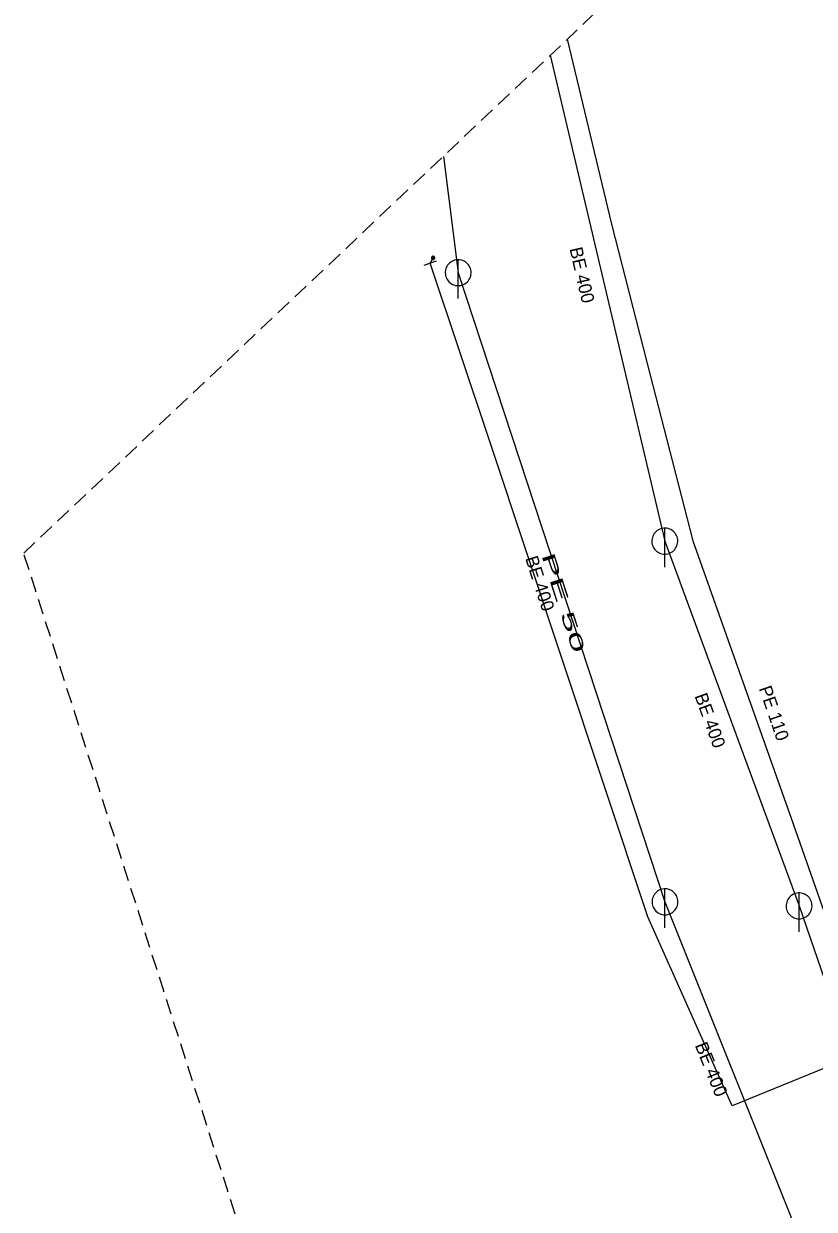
# Model space of a CAD drawing. Extents: x -779496 to -779026, y -977086 to -976624.
# Drawn here: x -779496.1 to -779435.1, y -977014.1 to -976922.6 of the extents above; entities that cross this region are included whole.
import ezdxf

# ---------------------------------------------------------------- set-up
doc = ezdxf.new("R2010")
doc.units = 0
doc.header["$LTSCALE"] = 0.4
doc.linetypes.add('MEDIUM_DASHED', pattern=[4.5, 3, -1.5])
for name, color, linetype, lineweight in [('1', 7, 'MEDIUM_DASHED', 25), ('14', 7, 'Continuous', 13), ('17', 7, 'Continuous', 25), ('22', 7, 'Continuous', 13), ('34', 7, 'Continuous', 13), ('9', 7, 'Continuous', 13)]:
    doc.layers.add(name, color=color, linetype=linetype, lineweight=lineweight)

msp = doc.modelspace()

# ---------------------------------------------------------------- linework, layer by layer
at = {"layer": '1'}
msp.add_lwpolyline([(-779144.045, -976624.23), (-779025.876, -976692.559), (-779211.57, -976955.425), (-779456.75, -977086.455), (-779496.14, -976963.463), (-779320.896, -976797.866)], close=True, dxfattribs=at)
at = {"layer": '14', "lineweight": 25}
for p, q in [((-779455.492, -976925.053), (-779446.649, -976962.53)), ((-779463.744, -976932.851), (-779462.598, -976941.824)), ((-779462.598, -976941.824), (-779446.634, -976990.353)), ((-779446.649, -976962.53), (-779436.28, -976990.67)), ((-779446.634, -976990.353), (-779436.14, -977016.59))]:
    msp.add_line(p, q, dxfattribs=at)
at = {"layer": '14'}
msp.add_line((-779464.768, -976941.099), (-779464.535, -976940.682), dxfattribs=at)
at = {"layer": '14', "lineweight": 25}
msp.add_lwpolyline([(-779436.28, -976990.67), (-779433.467, -976998.827), (-779431.048, -977007.721)], dxfattribs=at)
at = {"layer": '17'}
for points in [[(-779454.175, -976923.809), (-779450.772, -976938.068), (-779448.031, -976948.717), (-779444.473, -976962.508), (-779436.901, -976983.894), (-779434.181, -976991.585)], [(-779433.636, -977002.894), (-779441.438, -977006.098), (-779447.947, -976991.515), (-779454.579, -976971.633), (-779460.072, -976955.085), (-779464.768, -976941.099)]]:
    msp.add_lwpolyline(points, dxfattribs=at)
at = {"layer": '22'}
for p, q in [((-779462.598, -976943.824), (-779462.597, -976940.824)), ((-779446.649, -976964.53), (-779446.648, -976961.53)), ((-779446.634, -976992.353), (-779446.633, -976989.353)), ((-779436.28, -976992.67), (-779436.279, -976989.67))]:
    msp.add_line(p, q, dxfattribs=at)
for points in [[(-779461.598, -976941.824), (-779461.603, -976941.715), (-779461.621, -976941.607), (-779461.651, -976941.501), (-779461.691, -976941.4), (-779461.743, -976941.303), (-779461.805, -976941.213), (-779461.877, -976941.13), (-779461.957, -976941.056), (-779462.045, -976940.99), (-779462.139, -976940.935), (-779462.239, -976940.89), (-779462.344, -976940.857), (-779462.451, -976940.835), (-779462.56, -976940.825), (-779462.67, -976940.827), (-779462.778, -976940.841), (-779462.885, -976940.866), (-779462.988, -976940.903), (-779463.086, -976940.952), (-779463.178, -976941.01), (-779463.264, -976941.079), (-779463.341, -976941.156), (-779463.41, -976941.242), (-779463.469, -976941.334), (-779463.517, -976941.432), (-779463.554, -976941.535), (-779463.58, -976941.642), (-779463.594, -976941.75), (-779463.597, -976941.86), (-779463.587, -976941.969), (-779463.566, -976942.076), (-779463.532, -976942.18), (-779463.488, -976942.28), (-779463.433, -976942.375), (-779463.367, -976942.463), (-779463.293, -976942.543), (-779463.21, -976942.615), (-779463.12, -976942.677), (-779463.024, -976942.729), (-779462.922, -976942.77), (-779462.817, -976942.8), (-779462.709, -976942.818), (-779462.599, -976942.824), (-779462.49, -976942.818), (-779462.382, -976942.8), (-779462.277, -976942.771), (-779462.175, -976942.73), (-779462.078, -976942.678), (-779461.988, -976942.616), (-779461.905, -976942.545), (-779461.83, -976942.465), (-779461.765, -976942.377), (-779461.709, -976942.283), (-779461.665, -976942.183), (-779461.631, -976942.079), (-779461.609, -976941.971), (-779461.599, -976941.862)], [(-779445.649, -976962.53), (-779445.654, -976962.421), (-779445.672, -976962.313), (-779445.702, -976962.207), (-779445.742, -976962.106), (-779445.794, -976962.009), (-779445.856, -976961.919), (-779445.928, -976961.836), (-779446.008, -976961.762), (-779446.096, -976961.696), (-779446.19, -976961.641), (-779446.29, -976961.596), (-779446.395, -976961.563), (-779446.502, -976961.541), (-779446.611, -976961.531), (-779446.721, -976961.533), (-779446.829, -976961.547), (-779446.936, -976961.572), (-779447.039, -976961.609), (-779447.137, -976961.658), (-779447.229, -976961.716), (-779447.315, -976961.785), (-779447.392, -976961.862), (-779447.461, -976961.948), (-779447.52, -976962.04), (-779447.568, -976962.138), (-779447.605, -976962.241), (-779447.631, -976962.348), (-779447.645, -976962.456), (-779447.648, -976962.566), (-779447.638, -976962.675), (-779447.617, -976962.782), (-779447.583, -976962.886), (-779447.539, -976962.986), (-779447.484, -976963.081), (-779447.418, -976963.169), (-779447.344, -976963.249), (-779447.261, -976963.321), (-779447.171, -976963.383), (-779447.075, -976963.435), (-779446.973, -976963.476), (-779446.868, -976963.506), (-779446.76, -976963.524), (-779446.65, -976963.53), (-779446.541, -976963.524), (-779446.433, -976963.506), (-779446.328, -976963.477), (-779446.226, -976963.436), (-779446.129, -976963.384), (-779446.039, -976963.322), (-779445.956, -976963.251), (-779445.881, -976963.171), (-779445.816, -976963.083), (-779445.76, -976962.989), (-779445.716, -976962.889), (-779445.682, -976962.785), (-779445.66, -976962.677), (-779445.65, -976962.568)], [(-779445.634, -976990.353), (-779445.639, -976990.244), (-779445.657, -976990.136), (-779445.687, -976990.03), (-779445.727, -976989.929), (-779445.779, -976989.832), (-779445.841, -976989.742), (-779445.913, -976989.659), (-779445.993, -976989.585), (-779446.081, -976989.519), (-779446.175, -976989.464), (-779446.275, -976989.419), (-779446.38, -976989.386), (-779446.487, -976989.364), (-779446.596, -976989.354), (-779446.706, -976989.356), (-779446.814, -976989.37), (-779446.921, -976989.395), (-779447.024, -976989.432), (-779447.122, -976989.481), (-779447.214, -976989.539), (-779447.3, -976989.608), (-779447.377, -976989.685), (-779447.446, -976989.771), (-779447.505, -976989.863), (-779447.553, -976989.961), (-779447.59, -976990.064), (-779447.616, -976990.171), (-779447.63, -976990.279), (-779447.633, -976990.389), (-779447.623, -976990.498), (-779447.602, -976990.605), (-779447.568, -976990.709), (-779447.524, -976990.809), (-779447.469, -976990.904), (-779447.403, -976990.992), (-779447.329, -976991.072), (-779447.246, -976991.144), (-779447.156, -976991.206), (-779447.06, -976991.258), (-779446.958, -976991.299), (-779446.853, -976991.329), (-779446.745, -976991.347), (-779446.635, -976991.353), (-779446.526, -976991.347), (-779446.418, -976991.329), (-779446.313, -976991.3), (-779446.211, -976991.259), (-779446.114, -976991.207), (-779446.024, -976991.145), (-779445.941, -976991.074), (-779445.866, -976990.994), (-779445.801, -976990.906), (-779445.745, -976990.812), (-779445.701, -976990.712), (-779445.667, -976990.608), (-779445.645, -976990.5), (-779445.635, -976990.391)], [(-779435.28, -976990.67), (-779435.285, -976990.561), (-779435.303, -976990.453), (-779435.333, -976990.347), (-779435.373, -976990.246), (-779435.425, -976990.149), (-779435.487, -976990.059), (-779435.559, -976989.976), (-779435.639, -976989.902), (-779435.727, -976989.836), (-779435.821, -976989.781), (-779435.921, -976989.736), (-779436.026, -976989.703), (-779436.133, -976989.681), (-779436.242, -976989.671), (-779436.352, -976989.673), (-779436.46, -976989.687), (-779436.567, -976989.712), (-779436.67, -976989.749), (-779436.768, -976989.798), (-779436.86, -976989.856), (-779436.946, -976989.925), (-779437.023, -976990.002), (-779437.092, -976990.088), (-779437.151, -976990.18), (-779437.199, -976990.278), (-779437.236, -976990.381), (-779437.262, -976990.488), (-779437.276, -976990.596), (-779437.279, -976990.706), (-779437.269, -976990.815), (-779437.248, -976990.922), (-779437.214, -976991.026), (-779437.17, -976991.126), (-779437.115, -976991.221), (-779437.049, -976991.309), (-779436.975, -976991.389), (-779436.892, -976991.461), (-779436.802, -976991.523), (-779436.706, -976991.575), (-779436.604, -976991.616), (-779436.499, -976991.646), (-779436.391, -976991.664), (-779436.281, -976991.67), (-779436.172, -976991.664), (-779436.064, -976991.646), (-779435.959, -976991.617), (-779435.857, -976991.576), (-779435.76, -976991.524), (-779435.67, -976991.462), (-779435.587, -976991.391), (-779435.512, -976991.311), (-779435.447, -976991.223), (-779435.391, -976991.129), (-779435.347, -976991.029), (-779435.313, -976990.925), (-779435.291, -976990.817), (-779435.281, -976990.708)]]:
    msp.add_lwpolyline(points, close=True, dxfattribs=at)
at = {"layer": '34'}
msp.add_line((-779464.294, -976940.939), (-779465.242, -976941.257), dxfattribs=at)
at = {"layer": '9'}
for points in [[(-779464.661, -976940.682), (-779464.661, -976940.695), (-779464.659, -976940.708), (-779464.656, -976940.721), (-779464.651, -976940.733), (-779464.645, -976940.745), (-779464.638, -976940.756), (-779464.63, -976940.766), (-779464.62, -976940.776), (-779464.61, -976940.784), (-779464.599, -976940.791), (-779464.587, -976940.797), (-779464.575, -976940.802), (-779464.562, -976940.805), (-779464.549, -976940.807), (-779464.536, -976940.809), (-779464.523, -976940.808), (-779464.51, -976940.806), (-779464.497, -976940.803), (-779464.485, -976940.798), (-779464.473, -976940.792), (-779464.462, -976940.785), (-779464.452, -976940.777), (-779464.442, -976940.767), (-779464.434, -976940.757), (-779464.427, -976940.746), (-779464.421, -976940.734), (-779464.416, -976940.722), (-779464.413, -976940.709), (-779464.411, -976940.696), (-779464.409, -976940.683), (-779464.41, -976940.67), (-779464.412, -976940.657), (-779464.415, -976940.644), (-779464.42, -976940.632), (-779464.426, -976940.62), (-779464.433, -976940.609), (-779464.441, -976940.599), (-779464.451, -976940.589), (-779464.461, -976940.581), (-779464.472, -976940.574), (-779464.484, -976940.568), (-779464.496, -976940.563), (-779464.509, -976940.56), (-779464.522, -976940.558), (-779464.535, -976940.557), (-779464.548, -976940.557), (-779464.561, -976940.559), (-779464.574, -976940.562), (-779464.586, -976940.567), (-779464.598, -976940.573), (-779464.609, -976940.58), (-779464.619, -976940.588), (-779464.629, -976940.598), (-779464.637, -976940.608), (-779464.644, -976940.619), (-779464.65, -976940.631), (-779464.655, -976940.643), (-779464.658, -976940.656), (-779464.66, -976940.669)], [(-779464.641, -976940.682), (-779464.642, -976940.693), (-779464.64, -976940.704), (-779464.637, -976940.715), (-779464.633, -976940.725), (-779464.628, -976940.735), (-779464.622, -976940.744), (-779464.615, -976940.753), (-779464.607, -976940.761), (-779464.598, -976940.768), (-779464.589, -976940.774), (-779464.579, -976940.779), (-779464.569, -976940.783), (-779464.558, -976940.786), (-779464.547, -976940.789), (-779464.536, -976940.789), (-779464.525, -976940.789), (-779464.514, -976940.787), (-779464.503, -976940.784), (-779464.493, -976940.78), (-779464.483, -976940.775), (-779464.474, -976940.769), (-779464.465, -976940.762), (-779464.457, -976940.754), (-779464.45, -976940.745), (-779464.444, -976940.736), (-779464.439, -976940.726), (-779464.435, -976940.716), (-779464.432, -976940.705), (-779464.43, -976940.694), (-779464.429, -976940.683), (-779464.429, -976940.672), (-779464.431, -976940.661), (-779464.434, -976940.65), (-779464.438, -976940.64), (-779464.443, -976940.63), (-779464.449, -976940.621), (-779464.456, -976940.612), (-779464.464, -976940.604), (-779464.473, -976940.597), (-779464.482, -976940.591), (-779464.492, -976940.586), (-779464.502, -976940.582), (-779464.513, -976940.579), (-779464.524, -976940.577), (-779464.535, -976940.577), (-779464.546, -976940.576), (-779464.557, -976940.578), (-779464.568, -976940.581), (-779464.578, -976940.585), (-779464.588, -976940.59), (-779464.597, -976940.596), (-779464.606, -976940.603), (-779464.614, -976940.611), (-779464.621, -976940.62), (-779464.627, -976940.629), (-779464.632, -976940.639), (-779464.636, -976940.649), (-779464.639, -976940.66), (-779464.641, -976940.671)], [(-779464.622, -976940.682), (-779464.622, -976940.691), (-779464.621, -976940.7), (-779464.618, -976940.709), (-779464.615, -976940.717), (-779464.611, -976940.725), (-779464.606, -976940.733), (-779464.6, -976940.74), (-779464.594, -976940.746), (-779464.587, -976940.752), (-779464.579, -976940.757), (-779464.571, -976940.761), (-779464.563, -976940.764), (-779464.554, -976940.767), (-779464.545, -976940.768), (-779464.536, -976940.77), (-779464.527, -976940.769), (-779464.518, -976940.768), (-779464.509, -976940.765), (-779464.501, -976940.762), (-779464.493, -976940.758), (-779464.485, -976940.753), (-779464.478, -976940.747), (-779464.472, -976940.741), (-779464.466, -976940.734), (-779464.461, -976940.726), (-779464.457, -976940.718), (-779464.454, -976940.71), (-779464.451, -976940.701), (-779464.45, -976940.692), (-779464.448, -976940.683), (-779464.449, -976940.674), (-779464.45, -976940.665), (-779464.453, -976940.656), (-779464.456, -976940.648), (-779464.46, -976940.64), (-779464.465, -976940.632), (-779464.471, -976940.625), (-779464.477, -976940.619), (-779464.484, -976940.613), (-779464.492, -976940.608), (-779464.5, -976940.604), (-779464.508, -976940.601), (-779464.517, -976940.598), (-779464.526, -976940.597), (-779464.535, -976940.596), (-779464.544, -976940.596), (-779464.553, -976940.597), (-779464.562, -976940.6), (-779464.57, -976940.603), (-779464.578, -976940.607), (-779464.586, -976940.612), (-779464.593, -976940.618), (-779464.599, -976940.624), (-779464.605, -976940.631), (-779464.61, -976940.639), (-779464.614, -976940.647), (-779464.617, -976940.655), (-779464.62, -976940.664), (-779464.621, -976940.673)], [(-779464.602, -976940.682), (-779464.602, -976940.689), (-779464.601, -976940.696), (-779464.6, -976940.703), (-779464.597, -976940.709), (-779464.594, -976940.715), (-779464.59, -976940.721), (-779464.586, -976940.727), (-779464.581, -976940.732), (-779464.575, -976940.736), (-779464.569, -976940.74), (-779464.563, -976940.743), (-779464.557, -976940.746), (-779464.55, -976940.747), (-779464.543, -976940.75), (-779464.536, -976940.75), (-779464.529, -976940.75), (-779464.522, -976940.748), (-779464.515, -976940.747), (-779464.509, -976940.744), (-779464.502, -976940.741), (-779464.497, -976940.737), (-779464.491, -976940.733), (-779464.486, -976940.728), (-779464.482, -976940.722), (-779464.478, -976940.716), (-779464.475, -976940.71), (-779464.472, -976940.704), (-779464.47, -976940.697), (-779464.469, -976940.69), (-779464.468, -976940.683), (-779464.468, -976940.676), (-779464.469, -976940.669), (-779464.471, -976940.662), (-779464.474, -976940.656), (-779464.477, -976940.649), (-779464.481, -976940.644), (-779464.485, -976940.638), (-779464.49, -976940.633), (-779464.496, -976940.629), (-779464.501, -976940.625), (-779464.508, -976940.622), (-779464.514, -976940.619), (-779464.521, -976940.617), (-779464.528, -976940.616), (-779464.535, -976940.616), (-779464.542, -976940.616), (-779464.549, -976940.616), (-779464.556, -976940.618), (-779464.562, -976940.621), (-779464.568, -976940.624), (-779464.574, -976940.628), (-779464.58, -976940.632), (-779464.585, -976940.637), (-779464.589, -976940.643), (-779464.593, -976940.648), (-779464.596, -976940.655), (-779464.599, -976940.661), (-779464.6, -976940.668), (-779464.602, -976940.675)], [(-779464.582, -976940.682), (-779464.582, -976940.687), (-779464.582, -976940.692), (-779464.581, -976940.697), (-779464.579, -976940.701), (-779464.577, -976940.706), (-779464.574, -976940.71), (-779464.571, -976940.713), (-779464.567, -976940.717), (-779464.564, -976940.72), (-779464.56, -976940.723), (-779464.555, -976940.725), (-779464.551, -976940.727), (-779464.546, -976940.728), (-779464.541, -976940.73), (-779464.536, -976940.73), (-779464.531, -976940.73), (-779464.526, -976940.729), (-779464.521, -976940.728), (-779464.517, -976940.726), (-779464.512, -976940.724), (-779464.508, -976940.721), (-779464.504, -976940.718), (-779464.501, -976940.714), (-779464.498, -976940.711), (-779464.495, -976940.707), (-779464.493, -976940.702), (-779464.491, -976940.698), (-779464.49, -976940.693), (-779464.489, -976940.688), (-779464.488, -976940.683), (-779464.488, -976940.678), (-779464.489, -976940.673), (-779464.49, -976940.668), (-779464.492, -976940.664), (-779464.494, -976940.659), (-779464.497, -976940.655), (-779464.5, -976940.651), (-779464.503, -976940.648), (-779464.507, -976940.645), (-779464.511, -976940.642), (-779464.516, -976940.64), (-779464.52, -976940.638), (-779464.525, -976940.637), (-779464.53, -976940.636), (-779464.535, -976940.636), (-779464.54, -976940.636), (-779464.545, -976940.637), (-779464.55, -976940.637), (-779464.554, -976940.639), (-779464.559, -976940.641), (-779464.563, -976940.644), (-779464.566, -976940.647), (-779464.57, -976940.65), (-779464.573, -976940.654), (-779464.576, -976940.658), (-779464.578, -976940.663), (-779464.58, -976940.667), (-779464.581, -976940.672), (-779464.582, -976940.677)], [(-779464.562, -976940.682), (-779464.562, -976940.685), (-779464.563, -976940.688), (-779464.562, -976940.69), (-779464.561, -976940.693), (-779464.56, -976940.696), (-779464.558, -976940.698), (-779464.556, -976940.7), (-779464.554, -976940.702), (-779464.552, -976940.704), (-779464.55, -976940.706), (-779464.547, -976940.708), (-779464.544, -976940.709), (-779464.542, -976940.709), (-779464.539, -976940.71), (-779464.536, -976940.71), (-779464.533, -976940.71), (-779464.53, -976940.71), (-779464.527, -976940.709), (-779464.525, -976940.708), (-779464.522, -976940.707), (-779464.52, -976940.705), (-779464.517, -976940.703), (-779464.515, -976940.701), (-779464.514, -976940.699), (-779464.512, -976940.697), (-779464.511, -976940.694), (-779464.509, -976940.691), (-779464.509, -976940.689), (-779464.508, -976940.686), (-779464.507, -976940.683), (-779464.508, -976940.68), (-779464.508, -976940.677), (-779464.509, -976940.674), (-779464.51, -976940.672), (-779464.511, -976940.669), (-779464.513, -976940.667), (-779464.514, -976940.664), (-779464.516, -976940.662), (-779464.519, -976940.661), (-779464.521, -976940.659), (-779464.524, -976940.658), (-779464.526, -976940.657), (-779464.529, -976940.656), (-779464.532, -976940.656), (-779464.535, -976940.655), (-779464.538, -976940.656), (-779464.541, -976940.655), (-779464.543, -976940.657), (-779464.546, -976940.657), (-779464.549, -976940.658), (-779464.551, -976940.66), (-779464.553, -976940.661), (-779464.555, -976940.663), (-779464.557, -976940.666), (-779464.559, -976940.668), (-779464.56, -976940.671), (-779464.561, -976940.673), (-779464.562, -976940.676), (-779464.562, -976940.679)], [(-779464.543, -976940.682), (-779464.543, -976940.684), (-779464.543, -976940.684), (-779464.542, -976940.684), (-779464.542, -976940.686), (-779464.543, -976940.687), (-779464.541, -976940.687), (-779464.541, -976940.687), (-779464.541, -976940.689), (-779464.541, -976940.689), (-779464.54, -976940.69), (-779464.538, -976940.69), (-779464.538, -976940.69), (-779464.538, -976940.691), (-779464.536, -976940.691), (-779464.536, -976940.691), (-779464.535, -976940.691), (-779464.534, -976940.691), (-779464.534, -976940.69), (-779464.533, -976940.69), (-779464.531, -976940.69), (-779464.531, -976940.689), (-779464.531, -976940.689), (-779464.53, -976940.688), (-779464.53, -976940.688), (-779464.528, -976940.687), (-779464.528, -976940.686), (-779464.527, -976940.685), (-779464.527, -976940.685), (-779464.527, -976940.684), (-779464.527, -976940.683), (-779464.527, -976940.682), (-779464.527, -976940.681), (-779464.527, -976940.681), (-779464.528, -976940.68), (-779464.528, -976940.679), (-779464.529, -976940.678), (-779464.529, -976940.678), (-779464.53, -976940.677), (-779464.53, -976940.677), (-779464.531, -976940.676), (-779464.532, -976940.676), (-779464.533, -976940.675), (-779464.533, -976940.675), (-779464.534, -976940.675), (-779464.535, -976940.675), (-779464.536, -976940.675), (-779464.537, -976940.675), (-779464.537, -976940.675), (-779464.538, -976940.676), (-779464.539, -976940.675), (-779464.54, -976940.677), (-779464.54, -976940.677), (-779464.541, -976940.677), (-779464.541, -976940.677), (-779464.542, -976940.679), (-779464.542, -976940.68), (-779464.542, -976940.681), (-779464.543, -976940.681), (-779464.543, -976940.682)]]:
    msp.add_lwpolyline(points, close=True, dxfattribs=at)

# ---------------------------------------------------------------- texts
at = {"layer": '1'}
for s, rotation, p in [('BE 400', 283, (-779454.01, -976939.975)), ('BE 400', 288, (-779457.438, -976963.858)), ('PE 110', 289, (-779439.397, -976973.888)), ('BE 400', 290, (-779444.364, -976974.47)), ('BE 400', 292, (-779444.344, -977001.423))]:
    msp.add_text(s, height=1, rotation=rotation, dxfattribs=at).set_placement(p)
at = {"layer": '1', "width": 2.2}
msp.add_text('PE 50 ', height=1, rotation=288, dxfattribs=at).set_placement((-779456.187, -976963.614))

doc.saveas('drawing.dxf')
